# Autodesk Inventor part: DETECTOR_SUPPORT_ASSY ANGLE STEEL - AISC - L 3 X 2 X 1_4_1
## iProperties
Shininess: 64.0
Length Units: 11272
Angle Units: 11279
Time Units: 11290
Mass Units: 11286
Length Display Precision: 3
Angle Display Precision: 2
Compacted: True
Part Number: DETECTOR_SUPPORT_ASSY ANGLE STEEL - AISC - L 3 X 2 X 1_4_1
Document SubType Name: Modeling
Created: 2004-08
Designer: John Blackburn
Material: MILD_STEEL
Manufacturer: Standard
Standards Organization: Custom
Density: 0.0
Volumn: 0.0
Area: 0.0
PropertySet Name: Model Information
Control State: 0
Master: False
Checked Out: False
Author: John Blackburn
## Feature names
1. BaseExt [Extrusion]
2. SurfCut1_2
